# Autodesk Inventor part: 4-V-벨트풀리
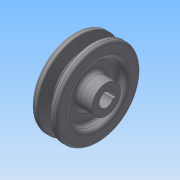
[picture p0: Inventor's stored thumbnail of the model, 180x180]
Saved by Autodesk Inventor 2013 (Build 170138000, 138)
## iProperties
Created: 2015-02
Part Number: 4-V-벨트풀리
Material: 일반
Document SubType Name: Modeling
Designer: Administrator
Density: 1 g/cm^3
Author: Administrator
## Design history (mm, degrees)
sketch "스케치1"
  geometry: L1 (0, 0)-(25, 0); L2 (25, 0)-(25, 11); L3 (25, 11)-(13, 11); L4 (13, 11)-(13, 21.5); L5 (13, 21.5)-(19, 21.5); L6 (19, 21.5)-(19, 32.5); L7 (19, 32.5)-(14.325, 32.5); L8 (14.325, 32.5)-(11.574, 23.5); L9 (11.574, 23.5)-(7.426, 23.5); L10 (7.426, 23.5)-(4.675, 32.5); L11 (4.675, 32.5)-(0, 32.5); L12 (0, 32.5)-(0, 21.5); L13 (0, 21.5)-(6, 21.5); L14 (6, 21.5)-(6, 11); L15 (6, 11)-(0, 11); L16 (0, 11)-(0, 0); 2 further points
  constraints: 32 end point, 7 parallel, 5 collinear, 4 perpendicular, 3 equal length, 2 point on line, 1 horizontal, 1 horizontal alignment, 1 vertical
  dimensions: "d0" = 25 distance of L1.start L1.end; "d2" = 2.7 distance from line of point (5.5, 29.8) L11; "d3" = 6.3 distance from line of L9 point (5.5, 29.8); "d4" = 8 distance of point (13.5, 29.8) point (5.5, 29.8); "d5" = 34 deg angle of L8 L10; "d6" = 19 distance between parallel lines of L6 L12; "d7" = 65 diameter of L7 L1; "d8" = 43 diameter of L5 L1; "d9" = 6 distance of L12.end L13.end; "d10" = 22 diameter of L3 L1
revolve "회전1" sketch "스케치1" stored, may be unused: angle "d11" = 90 deg
sketch "스케치2"
  geometry: L1 (-2, 5.123)-(-2, 7.3); L2 (-2, 7.3)-(2, 7.3); L3 (2, 7.3)-(2, 5.123); C1 r 11 at (0, 0) reference; A1 r 5.5 centre (0, 0) between (-2, 5.123) and (2, 5.123)
  constraints: 6 end point, 2 parallel, 2 point on circle, 1 centre point, 1 coincident, 1 perpendicular, 1 vertical
  dimensions: "d12" = 11 diameter of A1; "d14" = 4 distance of L1.end L2.end; "d15" = 12.8 dimension on A1 L2
extrude "돌출1" cut sketch "스케치2" stored distance "d16" = 10; taper "d17" = 0 deg
fillet "모깎기1" dims "d18" = 2, "d19" = 1, "d20" = 0.5, "d21" = 3
node "솔리드1"
